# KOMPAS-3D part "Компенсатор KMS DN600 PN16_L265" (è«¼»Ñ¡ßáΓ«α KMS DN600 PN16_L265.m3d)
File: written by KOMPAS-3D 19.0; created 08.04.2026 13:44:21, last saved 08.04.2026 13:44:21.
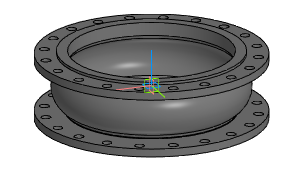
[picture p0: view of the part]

Document properties: Автор: Энергия; Полное имя файла: Z:\3.Личные\kachalov\3d для проектировщиков\7.1 Компенсатор\stp_Компенсатор KSM\Компенсатор KMS DN600 PN16_L265.m3d

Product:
- Part/product: Компенсатор KMS DN600 PN16_L265

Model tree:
1. Операция без истории:1  (labels: Компенсатор KMS DN600 PN16_L265)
